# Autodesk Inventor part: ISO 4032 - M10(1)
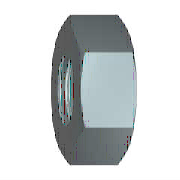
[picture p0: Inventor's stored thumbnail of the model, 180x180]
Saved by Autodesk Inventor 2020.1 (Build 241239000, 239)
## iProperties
Created: 2019-01
Part Number: ISO 4032 - M10(1)
Material: Edelstahl, 440C
Description: Sechskantmutter
Document SubType Name: Modeling
Standard: ISO 4032
Designer: lutzd
Standards Organization: DIN
Language: de-DE
Size Designation: M10
Categories: <MemberInstance><Categories><Category DisplayName="Verbindungselemente" InternalName="e4da775c-781d-43d5-af7c-5136215cf5a6" Mnemonic="FSTN"><Category DisplayNam
Mass: 10.4579 g
Surface Area: 9.47224 cm^2
Volume: 1.34941 cm^3
Density: 7.75 g/cm^3
Appearance: Semi-Polished(3)
IsCustomPart: 0
Author: lutzd
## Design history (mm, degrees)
workaxis "Work Axis1"
workplane "Work Plane1"
sketch "Skizze1"
  geometry: L1 (-9.238, 0)-(-4.619, 8); L2 (-4.619, 8)-(4.619, 8); L3 (4.619, 8)-(9.238, 0); L4 (9.238, 0)-(4.619, -8); L5 (4.619, -8)-(-4.619, -8); L6 (-4.619, -8)-(-9.238, 0); 2 further points
  constraints: 12 end point, 1 coincident, 1 horizontal, 11 other
  dimensions: "d0" = 18.47521 distance of L3.end L1.start (= 1.1547 x SW)
extrude "Körper" new body sketch "Skizze1" distance "d1" = 8.4 (= KOH); taper "d2" = 0 deg
sketch "Skizze2"
  geometry: L1 (0, 4.619)-(0, 9.238) reference; L2 (0, 9.238)-(8.4, 9.238) reference; L3 (8.4, 4.619)-(8.4, 9.238) reference; L4 (-1.68, 0)-(10.08, 0) reference; L5 (1.119, 9.238)-(0, 7.3); L6 (7.281, 9.238)-(8.4, 7.3)
  constraints: 4 end point, 4 point on line
  dimensions: "d3" = 30 deg angle of L1 L5 (= ANG1); "d4" = 30 deg angle of L3 L6 (= ANG2); "d5" = 14.6 diameter of L5.end L4 (= SW0); "d6" = 14.6 diameter of L6.end L4 (= SW01)
revolve "Fase1" stored, may be unused: angle "d7" = 90 deg
sketch "Skizze3"
  geometry: 4 further points
  constraints: 1 coincident, 1 other
hole "Gewinde" sketch "Skizze3" diameter "d25" = 8.376; stored, may be unused: countersink angle "d29" = 82 deg, drill point angle "d31" = 118 deg; dims "d26" = 6, "d27" = 4, "d28" = 2, "d30" = 8
body "Solid1"
chamfer "Fase2" distance "d8" = 0.8119 (= -0.5 x GD1 + 0.5 x NND); stored, may be unused: angle "d9" = 30 deg, second distance "d40" = 0.8119 (= -0.5 x GD1 + 0.5 x NND)
chamfer "Fase3" distance "d10" = 0.8119 (= -0.5 x GD1 + 0.5 x NND); stored, may be unused: angle "d11" = 30 deg, second distance "d41" = 0.8119 (= -0.5 x GD1 + 0.5 x NND)
other parameters: "ANG1" = 30 deg [user parameter; used in 1 equation term], "ANG2" = 30 deg [user parameter; used in 1 equation term], "KOH" = 8.4 [user parameter; used in 1 equation term], "SW" = 16 [user parameter; used in 2 equation terms], "SW0" = 14.6 [user parameter; used in 1 equation term], "SW01" = 14.6 [user parameter; used in 1 equation term], "GD1" = 8.3762 (computed from THREADDIA, PTC, TOA) [user parameter; used in 4 equation terms], "d13" = 0, "d14" = 0, "d39" = 0, "d42" = 0, "GUL" = 0.8119 (= 0.541266 x PTC) [user parameter], "TPU" = 6.66667 (computed from PTC) [user parameter], "TOA" = 30 deg [user parameter; used in 1 equation term], "PTC" = 1.5 [user parameter; used in 4 equation terms], "E0" = 18.48 (= 1.155 x SW) [user parameter], "GAL" = 0.8119 (= 0.541266 x PTC) [user parameter]
